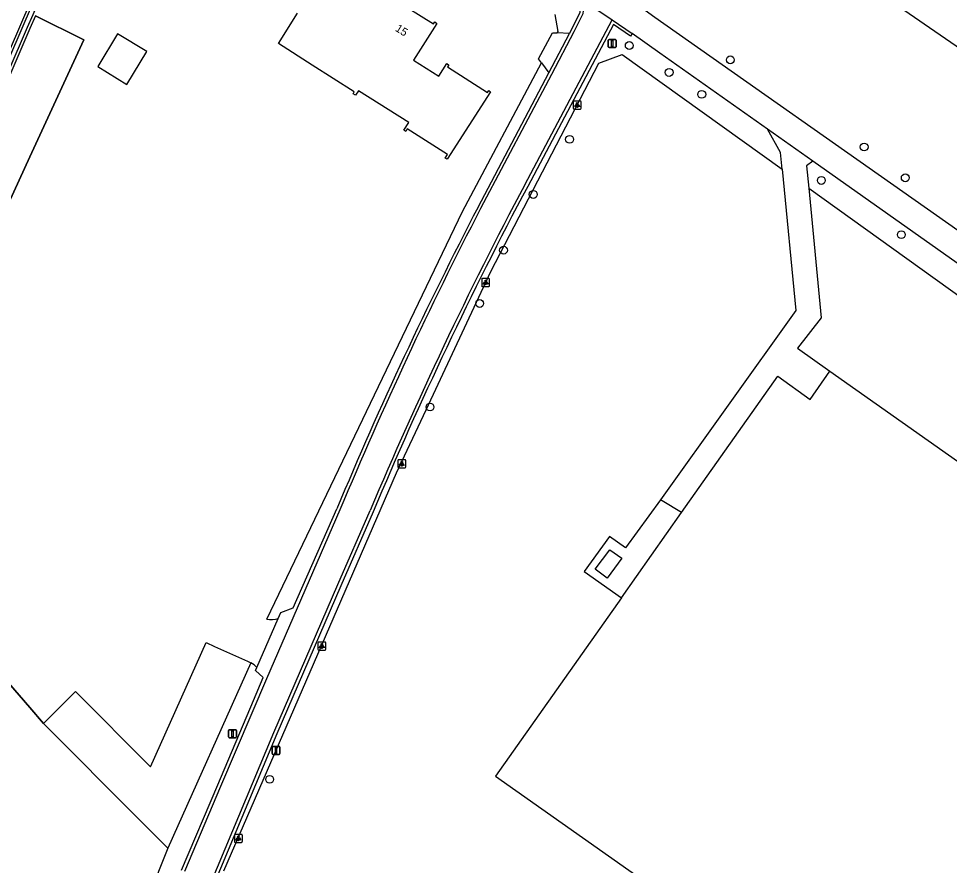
# Model space of a CAD drawing. Extents: x 155209 to 156823, y 385356 to 388482.
# Drawn here: x 155998.6 to 156114.9, y 386038.3 to 386144.1 of the extents above; entities that cross this region are included whole.
import ezdxf

# ---------------------------------------------------------------- set-up
doc = ezdxf.new("R2010")
doc.units = 0
for name, color, linetype in [('IMGEO_Berm_groen', 7, 'Continuous'), ('IMGEO_Berm_open', 7, 'Continuous'), ('IMGEO_Boom', 7, 'Continuous'), ('IMGEO_Groenvoorziening', 7, 'Continuous'), ('IMGEO_Hek', 7, 'Continuous'), ('IMGEO_Lage_trafo', 7, 'Continuous'), ('IMGEO_Lichtpunt', 7, 'Continuous'), ('IMGEO_Naaldbos', 7, 'Continuous'), ('IMGEO_Pand', 7, 'Continuous'), ('IMGEO_Pand_nummerreeks', 7, 'Continuous'), ('IMGEO_Parkeervlak_gesloten', 7, 'Continuous'), ('IMGEO_Rijbaan_lokaal_gesloten', 7, 'Continuous'), ('IMGEO_Rijbaan_lokaal_open', 7, 'Continuous'), ('IMGEO_Verkeersbordpaal', 7, 'Continuous'), ('IMGEO_Voetpad_halfverhard', 7, 'Continuous'), ('IMGEO_Voetpad_open', 7, 'Continuous'), ('IMGEO_Waterloop', 7, 'Continuous')]:
    doc.layers.add(name, color=color, linetype=linetype)

msp = doc.modelspace()

# ---------------------------------------------------------------- linework, layer by layer
at = {"layer": 'IMGEO_Berm_groen'}
for points in [[(156013.5, 386177.7), (156000, 386146), (155952.02, 386034.68)], [(156065.9, 386142.27), (156066.01, 386142.46), (156065.66, 386144.59)], [(156024.22, 386037.59), (156045.81, 386087.34), (156049.5, 386095.21), (156057.59, 386112.46), (156071.11, 386138.48), (156074.02, 386139.6), (156094.02, 386125.25)], [(156097.33, 386122.88), (156148.23, 386086.38)], [(156017.22, 386040.43), (155993.88, 385981.94), (155984.26, 385961.78), (155979.58, 385953.33)]]:
    msp.add_lwpolyline(points, dxfattribs=at)
msp.add_arc((156026.48, 386061.45), 2.44, 39.5677, 61.9809, dxfattribs=at)
at = {"layer": 'IMGEO_Berm_open'}
for points in [[(156067.9, 386147.28), (156067.67, 386146.89), (156068.51, 386146.37), (156068.81, 386145.67), (156068.71, 386144.84), (156067.43, 386142.22)], [(156075.27, 386142.2), (156075.05, 386141.86), (156072.94, 386143.34), (156062.21, 386123.11)], [(156056, 386120.53), (156064.83, 386137.29)], [(156042.89, 386082.44), (156038.86, 386073.22), (156030.85, 386054.72), (156018.71, 386025.67)], [(156031.03, 386069.11), (156031.37, 386069.88), (156032.91, 386070.46), (156038.35, 386082.83)], [(156028.36, 386063), (156031.03, 386069.11)], [(156018.96, 386037.69), (156023.47, 386048.35), (156027.93, 386058.88), (156029.15, 386061.75), (156028.19, 386062.62), (156028.36, 386063)]]:
    msp.add_lwpolyline(points, dxfattribs=at)
for centre, radius, start, end in [((156497.69, 385891.37), 493.3, 151.9805, 157.2124), ((156497.11, 385891.09), 497.21, 152.5191, 157.317)]:
    msp.add_arc(centre, radius, start, end, dxfattribs=at)
at = {"layer": 'IMGEO_Boom'}
for centre in [(156074.9, 386140.7), (156087.53, 386138.91), (156079.88, 386137.34), (156083.96, 386134.6), (156067.44, 386128.98), (156104.25, 386128.03), (156098.9, 386123.85), (156109.39, 386124.18), (156062.9, 386122.1), (156108.9, 386117.07), (156059.19, 386115.13), (156056.2, 386108.48), (156050, 386095.54), (156029.97, 386049.03)]:
    msp.add_circle(centre, 0.489, dxfattribs=at)
at = {"layer": 'IMGEO_Groenvoorziening'}
msp.add_lwpolyline([(156029.6, 386069.06), (156054.04, 386119.95), (156063.93, 386138.54)], dxfattribs=at)
msp.add_arc((156030.19, 386072.38), 3.37, 259.8828, 284.4364, dxfattribs=at)
at = {"layer": 'IMGEO_Hek'}
for points in [[(155979.68, 386081.47), (155987.48, 386099.58), (156000, 386126.8), (156006.74, 386141.43), (156000.68, 386144.39)], [(156001.7, 386056.03), (156000, 386057.99), (155979.68, 386081.47)]]:
    msp.add_lwpolyline(points, dxfattribs=at)
at = {"layer": 'IMGEO_Lage_trafo'}
msp.add_lwpolyline([(156072.46, 386077.69), (156073.97, 386076.68), (156072.15, 386074.18), (156070.64, 386075.27), (156072.46, 386077.69)], dxfattribs=at)
at = {"layer": 'IMGEO_Lichtpunt'}
for p, q in [((156067.89, 386133.67), (156067.89, 386132.86)), ((156067.89, 386133.67), (156067.89, 386132.86)), ((156068.8, 386133.77), (156067.99, 386133.77)), ((156068.8, 386133.77), (156067.99, 386133.77)), ((156068.89, 386132.86), (156068.89, 386133.67)), ((156068.89, 386132.86), (156068.89, 386133.67)), ((156067.99, 386132.77), (156068.8, 386132.77)), ((156067.99, 386132.77), (156068.8, 386132.77)), ((156056.46, 386111.51), (156056.46, 386110.7)), ((156056.46, 386111.51), (156056.46, 386110.7)), ((156057.36, 386111.61), (156056.55, 386111.61)), ((156057.36, 386111.61), (156056.55, 386111.61)), ((156057.45, 386110.7), (156057.45, 386111.51)), ((156057.45, 386110.7), (156057.45, 386111.51)), ((156056.55, 386110.61), (156057.36, 386110.61)), ((156056.55, 386110.61), (156057.36, 386110.61)), ((156045.98, 386088.86), (156045.98, 386088.06)), ((156045.98, 386088.86), (156045.98, 386088.06)), ((156046.88, 386088.96), (156046.07, 386088.96)), ((156046.88, 386088.96), (156046.07, 386088.96)), ((156046.97, 386088.06), (156046.97, 386088.86)), ((156046.97, 386088.06), (156046.97, 386088.86)), ((156046.07, 386087.96), (156046.88, 386087.96)), ((156046.07, 386087.96), (156046.88, 386087.96)), ((156035.98, 386066.1), (156035.98, 386065.29)), ((156035.98, 386066.1), (156035.98, 386065.29)), ((156036.89, 386066.19), (156036.08, 386066.19)), ((156036.89, 386066.19), (156036.08, 386066.19)), ((156036.98, 386065.29), (156036.98, 386066.1)), ((156036.98, 386065.29), (156036.98, 386066.1)), ((156036.08, 386065.19), (156036.89, 386065.19)), ((156036.08, 386065.19), (156036.89, 386065.19)), ((156025.55, 386042.06), (156025.55, 386041.26)), ((156025.55, 386042.06), (156025.55, 386041.26)), ((156026.45, 386042.16), (156025.65, 386042.16)), ((156026.45, 386042.16), (156025.65, 386042.16)), ((156026.55, 386041.26), (156026.55, 386042.06)), ((156026.55, 386041.26), (156026.55, 386042.06)), ((156025.65, 386041.16), (156026.45, 386041.16)), ((156025.65, 386041.16), (156026.45, 386041.16))]:
    msp.add_line(p, q, dxfattribs=at)
for points in [[(156068.27, 386133.33), (156068.31, 386133.31), (156068.12, 386133.04), (156068.08, 386133.07), (156068.27, 386133.33)], [(156068.37, 386133.29), (156068.42, 386133.29), (156068.42, 386132.96), (156068.37, 386132.96), (156068.37, 386133.29)], [(156068.48, 386133.31), (156068.52, 386133.33), (156068.7, 386133.07), (156068.67, 386133.04), (156068.48, 386133.31)], [(156056.83, 386111.17), (156056.87, 386111.15), (156056.68, 386110.88), (156056.64, 386110.91), (156056.83, 386111.17)], [(156056.93, 386111.13), (156056.98, 386111.13), (156056.98, 386110.8), (156056.93, 386110.8), (156056.93, 386111.13)], [(156057.04, 386111.15), (156057.08, 386111.17), (156057.27, 386110.91), (156057.23, 386110.88), (156057.04, 386111.15)], [(156046.35, 386088.53), (156046.39, 386088.5), (156046.2, 386088.24), (156046.16, 386088.26), (156046.35, 386088.53)], [(156046.45, 386088.48), (156046.5, 386088.48), (156046.5, 386088.16), (156046.45, 386088.16), (156046.45, 386088.48)], [(156046.56, 386088.5), (156046.6, 386088.53), (156046.79, 386088.26), (156046.75, 386088.24), (156046.56, 386088.5)], [(156036.36, 386065.76), (156036.4, 386065.73), (156036.21, 386065.47), (156036.17, 386065.5), (156036.36, 386065.76)], [(156036.46, 386065.71), (156036.51, 386065.71), (156036.51, 386065.39), (156036.46, 386065.39), (156036.46, 386065.71)], [(156036.57, 386065.73), (156036.61, 386065.76), (156036.79, 386065.5), (156036.76, 386065.47), (156036.57, 386065.73)], [(156025.93, 386041.73), (156025.96, 386041.7), (156025.78, 386041.44), (156025.74, 386041.46), (156025.93, 386041.73)], [(156026.03, 386041.68), (156026.08, 386041.68), (156026.08, 386041.36), (156026.03, 386041.36), (156026.03, 386041.68)], [(156026.14, 386041.7), (156026.18, 386041.73), (156026.36, 386041.46), (156026.32, 386041.44), (156026.14, 386041.7)]]:
    msp.add_lwpolyline(points, dxfattribs=at)
for centre in [(156068.39, 386133.47), (156056.96, 386111.31), (156046.48, 386088.66), (156036.48, 386065.89), (156026.05, 386041.86)]:
    msp.add_circle(centre, 0.0994, dxfattribs=at)
for centre, start, end in [((156067.99, 386133.67), 90, 180), ((156067.99, 386133.67), 90, 180), ((156068.8, 386133.67), 0, 90), ((156068.8, 386133.67), 0, 90), ((156067.99, 386132.86), 180, 270), ((156067.99, 386132.86), 180, 270), ((156068.8, 386132.86), 270, 0), ((156068.8, 386132.86), 270, 360), ((156056.55, 386111.51), 90, 180), ((156056.55, 386111.51), 90, 180), ((156057.36, 386111.51), 0, 90), ((156057.36, 386111.51), 0, 90), ((156056.55, 386110.7), 180, 270), ((156056.55, 386110.7), 180, 270), ((156057.36, 386110.7), 270, 0), ((156057.36, 386110.7), 270, 360), ((156046.07, 386088.86), 90, 180), ((156046.07, 386088.86), 90, 180), ((156046.07, 386088.06), 180, 270), ((156046.07, 386088.06), 180, 270), ((156046.88, 386088.86), 0, 90), ((156046.88, 386088.86), 0, 90), ((156046.88, 386088.06), 270, 0), ((156046.88, 386088.06), 270, 360), ((156036.08, 386066.1), 90, 180), ((156036.08, 386066.1), 90, 180), ((156036.89, 386066.1), 0, 90), ((156036.89, 386066.1), 0, 90), ((156036.08, 386065.29), 180, 270), ((156036.08, 386065.29), 180, 270), ((156036.89, 386065.29), 270, 0), ((156036.89, 386065.29), 270, 360), ((156025.65, 386042.06), 90, 180), ((156025.65, 386042.06), 90, 180), ((156026.45, 386042.06), 0, 90), ((156026.45, 386042.06), 0, 90), ((156025.65, 386041.26), 180, 270), ((156025.65, 386041.26), 180, 270), ((156026.45, 386041.26), 270, 0), ((156026.45, 386041.26), 270, 360)]:
    msp.add_arc(centre, 0.0946, start, end, dxfattribs=at)
at = {"layer": 'IMGEO_Naaldbos'}
for points in [[(156000.68, 386144.39), (156000, 386142.83), (155975.49, 386085.88), (155975.71, 386085.5)], [(156000.68, 386144.39), (156006.74, 386141.43), (156000, 386126.8), (155987.48, 386099.58), (155979.68, 386081.47)], [(155979.68, 386081.47), (156000, 386057.99), (156001.7, 386056.03)]]:
    msp.add_lwpolyline(points, dxfattribs=at)
at = {"layer": 'IMGEO_Pand'}
for points in [[(156045.47, 386146.54), (156050.43, 386143.39), (156050.59, 386143.64), (156050.87, 386143.46), (156047.95, 386138.87), (156051.1, 386136.88), (156052.11, 386138.44), (156052.35, 386138.26), (156052.19, 386138.03), (156057.17, 386134.82), (156057.34, 386135.08), (156057.57, 386134.92), (156052.15, 386126.49), (156051.91, 386126.63), (156052.18, 386127.07), (156047.16, 386130.28), (156046.96, 386129.97), (156046.74, 386130.11), (156047.35, 386131.07), (156041.05, 386135.06)], [(156041.05, 386135.06), (156040.7, 386134.49), (156040.39, 386134.68), (156040.54, 386134.91), (156035.27, 386138.26), (156031.05, 386140.94), (156033.46, 386144.75)], [(156012.13, 386135.85), (156014.6, 386139.94), (156010.94, 386142.15), (156008.47, 386138.07), (156012.13, 386135.85)], [(156001.7, 386056.03), (156005.69, 386060.01), (156015.07, 386050.58), (156022.04, 386066.11), (156023.06, 386065.65), (156027.21, 386063.79), (156027.62, 386063.6)], [(156027.62, 386063.6), (156017.22, 386040.43)], [(156017.22, 386040.43), (156013.69, 386043.98), (156001.7, 386056.03)]]:
    msp.add_lwpolyline(points, dxfattribs=at)
at = {"layer": 'IMGEO_Parkeervlak_gesloten'}
for points in [[(156099.96, 386100.04), (156160, 386057.7), (156157.51, 386054.17), (156161.54, 386051.34)], [(156073.91, 386071.73), (156058.17, 386049.45), (156094.05, 386024.14)]]:
    msp.add_lwpolyline(points, dxfattribs=at)
at = {"layer": 'IMGEO_Rijbaan_lokaal_gesloten'}
for points in [[(156166.86, 386105.42), (156156.69, 386112.43), (156153.6, 386114.56), (156143.24, 386121.7), (156086.24, 386160.94), (156083.54, 386162.84)], [(156068.86, 386146.59), (156069.24, 386145.9), (156069.08, 386144.68), (156067.96, 386142.42), (156065.18, 386137.08), (156056.32, 386120.34)], [(156068.86, 386146.59), (156072.75, 386143.92)], [(156153.85, 386090.94), (156151.39, 386092.68), (156148.48, 386094.74), (156078.08, 386144.22), (156076.42, 386145.39), (156074.85, 386146.49)], [(156061.83, 386123.29), (156072.75, 386143.92)], [(156072.75, 386143.92), (156075.27, 386142.2)], [(156092.18, 386130.24), (156078.71, 386139.75), (156075.27, 386142.2)], [(156097.82, 386126.26), (156092.18, 386130.24)], [(156209.24, 386046.84), (156203.46, 386051.76), (156174.48, 386072.45), (156135.52, 386099.82), (156125.95, 386106.41), (156097.82, 386126.26)], [(156018.34, 386025.82), (156030.47, 386054.89), (156038.47, 386073.36), (156042.51, 386082.62)], [(156038.74, 386082.69), (156029.56, 386061.6), (156023.82, 386048.16), (156019.32, 386037.52)]]:
    msp.add_lwpolyline(points, dxfattribs=at)
for centre, radius, start, end in [((156513.1, 385884.08), 510.75, 152.0725, 157.1251), ((156504.59, 385888.19), 504.82, 152.6219, 157.3392)]:
    msp.add_arc(centre, radius, start, end, dxfattribs=at)
at = {"layer": 'IMGEO_Rijbaan_lokaal_open'}
for points in [[(156063.93, 386138.54), (156063.57, 386139.03), (156065.32, 386142.28), (156065.9, 386142.27)], [(156064.83, 386137.29), (156067.43, 386142.22)], [(156067.43, 386142.22), (156065.9, 386142.27)], [(156063.93, 386138.54), (156064.83, 386137.29)]]:
    msp.add_lwpolyline(points, dxfattribs=at)
at = {"layer": 'IMGEO_Verkeersbordpaal'}
for p, q in [((156072.28, 386140.55), (156072.28, 386141.35)), ((156072.28, 386141.35), (156072.28, 386140.55)), ((156072.38, 386141.45), (156073.17, 386141.45)), ((156073.17, 386141.45), (156072.38, 386141.45)), ((156073.17, 386140.45), (156072.38, 386140.45)), ((156072.38, 386140.45), (156073.17, 386140.45)), ((156073.27, 386141.35), (156073.27, 386140.55)), ((156073.27, 386140.55), (156073.27, 386141.35)), ((156024.82, 386054.33), (156024.82, 386055.13)), ((156024.82, 386055.13), (156024.82, 386054.33)), ((156024.92, 386055.23), (156025.7, 386055.23)), ((156025.7, 386055.23), (156024.92, 386055.23)), ((156025.8, 386055.13), (156025.8, 386054.33)), ((156025.8, 386054.33), (156025.8, 386055.13)), ((156025.7, 386054.23), (156024.92, 386054.23)), ((156024.92, 386054.23), (156025.7, 386054.23)), ((156030.36, 386053.15), (156031.15, 386053.15)), ((156031.15, 386053.15), (156030.36, 386053.15)), ((156030.26, 386052.25), (156030.26, 386053.05)), ((156030.26, 386053.05), (156030.26, 386052.25)), ((156031.15, 386052.15), (156030.36, 386052.15)), ((156030.36, 386052.15), (156031.15, 386052.15)), ((156031.25, 386053.05), (156031.25, 386052.25)), ((156031.25, 386052.25), (156031.25, 386053.05))]:
    msp.add_line(p, q, dxfattribs=at)
for points in [[(156072.7, 386141.32), (156072.85, 386141.32), (156072.85, 386140.57), (156072.7, 386140.57), (156072.7, 386141.32)], [(156025.24, 386055.1), (156025.39, 386055.1), (156025.39, 386054.35), (156025.24, 386054.35), (156025.24, 386055.1)], [(156030.68, 386053.03), (156030.83, 386053.03), (156030.83, 386052.28), (156030.68, 386052.28), (156030.68, 386053.03)]]:
    msp.add_lwpolyline(points, dxfattribs=at)
for centre, start, end in [((156072.38, 386141.35), 90, 180), ((156072.38, 386141.35), 90, 180), ((156072.38, 386140.55), 180, 270), ((156072.38, 386140.55), 180, 270), ((156073.17, 386141.35), 0, 90), ((156073.17, 386141.35), 360, 90), ((156073.17, 386140.55), 270, 0), ((156073.17, 386140.55), 270, 0), ((156024.92, 386055.13), 90, 180), ((156024.92, 386055.13), 90, 180), ((156024.92, 386054.33), 180, 270), ((156024.92, 386054.33), 180, 270), ((156025.7, 386055.13), 0, 90), ((156025.7, 386055.13), 360, 90), ((156025.7, 386054.33), 270, 0), ((156025.7, 386054.33), 270, 0), ((156030.36, 386053.05), 90, 180), ((156030.36, 386053.05), 90, 180), ((156031.15, 386053.05), 0, 90), ((156031.15, 386053.05), 360, 90), ((156030.36, 386052.25), 180, 270), ((156030.36, 386052.25), 180, 270), ((156031.15, 386052.25), 270, 0), ((156031.15, 386052.25), 270, 0)]:
    msp.add_arc(centre, 0.1, start, end, dxfattribs=at)
at = {"layer": 'IMGEO_Voetpad_halfverhard'}
for points in [[(156078.82, 386083.96), (156074.43, 386077.96), (156072.41, 386079.35), (156069.27, 386075.01), (156073.91, 386071.73)], [(156073.91, 386071.73), (156081.42, 386082.36)]]:
    msp.add_lwpolyline(points, dxfattribs=at)
at = {"layer": 'IMGEO_Voetpad_open'}
for points in [[(156094.02, 386125.25), (156093.82, 386127.35), (156092.18, 386130.24)], [(156097.82, 386126.26), (156097.06, 386125.69), (156097.33, 386122.88)], [(156094.02, 386125.25), (156095.72, 386107.6), (156078.82, 386083.96)], [(156097.33, 386122.88), (156098.87, 386106.67), (156095.93, 386102.88), (156099.96, 386100.04)], [(156081.42, 386082.36), (156093.46, 386099.39), (156097.49, 386096.49), (156099.96, 386100.04)], [(156081.42, 386082.36), (156079.03, 386083.83), (156078.82, 386083.96)]]:
    msp.add_lwpolyline(points, dxfattribs=at)
at = {"layer": 'IMGEO_Waterloop'}
for points in [[(156015.54, 386179.18), (156015.76, 386179.19), (156015.84, 386179.15), (156015.91, 386178.56), (156028.73, 386169.96), (156048.81, 386156.86), (156048.58, 386156.51), (156048.41, 386156.24), (156033.05, 386166.23), (156015.52, 386177.85), (156015.03, 386177.92), (156014.67, 386177.6), (156000.35, 386144.53), (155999.67, 386142.97), (155975.09, 386085.85), (155975.31, 386085.48), (155942.79, 386010.26)], [(155942.79, 386010.26), (155942.16, 386010.92), (156000.33, 386145.86), (156013.83, 386177.55)]]:
    msp.add_lwpolyline(points, dxfattribs=at)

# ---------------------------------------------------------------- texts
at = {"layer": 'IMGEO_Pand_nummerreeks'}
msp.add_text('15', height=1, rotation=327.605, dxfattribs=at).set_placement((156045.57, 386142.59))

doc.saveas('drawing.dxf')
